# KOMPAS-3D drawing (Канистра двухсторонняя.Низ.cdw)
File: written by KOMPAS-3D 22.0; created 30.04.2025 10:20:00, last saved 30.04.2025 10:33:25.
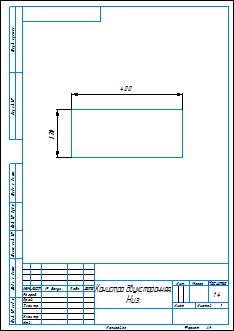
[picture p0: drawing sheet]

Sheet 1: A4, portrait

Document properties: Автор: Admin; Наименование: Канистра двухсторонняя. Низ; Полное имя файла: D:\28.11.2016\3D модели\Абилимпикс\2025\Канистра двухсторонняя\Канистра двухсторонняя.Низ.cdw

Title block, sheet 1: Наименование: Канистра двухсторонняя. / Низ.; scale: 1:4; Количество листов документа: 1; Форматы листов документа: A4; stored path: D:\28.11.2016\3D модели\Абилимпикс\2025\Канистра двухсторонняя\Канистра двухсторонняя.Боковина.cdw

Dimensions and other numbers on the sheet: 400; 170; 1:4; 1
